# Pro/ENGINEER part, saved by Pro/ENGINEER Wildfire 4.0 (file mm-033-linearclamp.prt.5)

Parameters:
  METRIC = "NO"

Other parameters: PITCH, DRILL_DIAMETER, THREAD_DIAMETER, THREADS_PER_INCH, DRILL_POINT_ANGLE, DRILL_DEPTH, THREAD_DEPTH, THREAD_LENGTH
